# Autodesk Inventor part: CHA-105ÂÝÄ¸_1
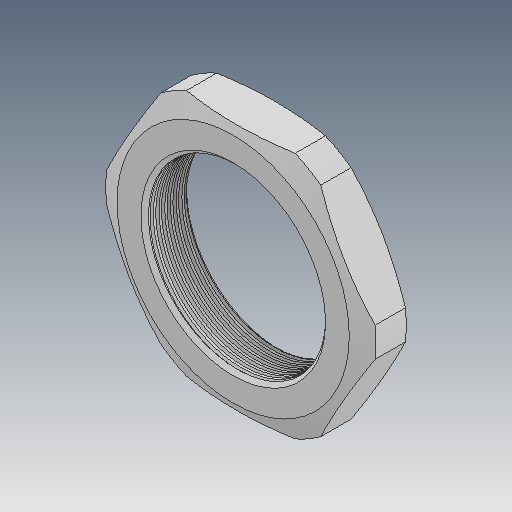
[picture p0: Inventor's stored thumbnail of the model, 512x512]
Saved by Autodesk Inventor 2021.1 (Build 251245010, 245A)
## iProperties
Created: 2019-12
Part Number: CHA-105ÂÝÄ¸_1
Material: Ogólny
Document SubType Name: Modeling
Designer: user
Density: 1 g/cm^3
Appearance: Domyślna
Author: user
Revision Number: ÈÎºÎ
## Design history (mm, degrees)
feature "ÊäÈë1"
node "Bryła1"
